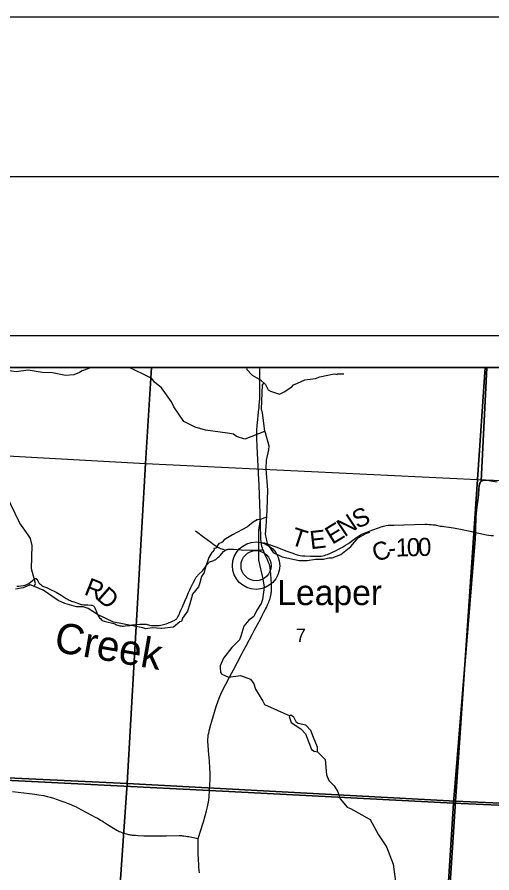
# Model space of a CAD drawing. Extents: x -2.1 to 31.9, y 6.3 to 28.3.
# Drawn here: x 3.259 to 4.749, y 25.658 to 28.344 of the extents above; entities that cross this region are included whole.
import ezdxf

# ---------------------------------------------------------------- set-up
doc = ezdxf.new("R2010")
doc.units = 0
for name, color, linetype in [('Default', 7, 'Continuous'), ('GM_X_County_Road', 7, 'Continuous'), ('GM_X_County_Road_Text', 7, 'Continuous'), ('GM_X_Minor_River', 7, 'Continuous'), ('GM_X_Minor_River_Text', 7, 'Continuous'), ('GM_X_Section', 7, 'Continuous'), ('GM_X_Section_Text', 7, 'Continuous'), ('GM_X_State_Route', 7, 'Continuous'), ('GM_X_Township_Road', 7, 'Continuous'), ('GM_X_Unincorporated', 7, 'Continuous'), ('GM_X_Unincorporated_Location', 7, 'Continuous'), ('GM_X_Unincorporated_Text', 7, 'Continuous'), ('SH_Border', 7, 'Continuous'), ('SH_Cut_Line', 7, 'Continuous'), ('SH_Data', 7, 'Continuous')]:
    doc.layers.add(name, color=color, linetype=linetype)

msp = doc.modelspace()

# ---------------------------------------------------------------- linework, layer by layer
at = {"layer": 'Default'}
for points in [[(3.0763, 25.9555), (3.8625, 25.9158), (4.6286, 25.8765), (4.6962, 26.7048), (4.6976, 26.7271), (4.6976, 26.7313), (4.6974, 26.7458), (4.6982, 26.7628), (4.6989, 26.7745), (4.6998, 26.7857), (4.7008, 26.7966), (4.7027, 26.8132), (4.7045, 26.8279), (4.7064, 26.8439), (4.7081, 26.8648), (4.7086, 26.8693), (4.7092, 26.8741), (4.7097, 26.8767), (4.7104, 26.879), (4.7116, 26.8819), (4.713, 26.8843), (4.7143, 26.8861), (4.7151, 26.8869), (4.7153, 26.887), (4.7331, 27.244), (0.0344, 27.244)], [(6.8344, 27.244), (4.7331, 27.244), (4.7153, 26.887), (4.7151, 26.8869), (4.7143, 26.8861), (4.713, 26.8843), (4.7116, 26.8819), (4.7104, 26.879), (4.7097, 26.8767), (4.7092, 26.8741), (4.7086, 26.8693), (4.7081, 26.8648), (4.7064, 26.8439), (4.7045, 26.8279), (4.7027, 26.8132), (4.7008, 26.7966), (4.6998, 26.7857), (4.6989, 26.7745), (4.6982, 26.7628), (4.6974, 26.7458), (4.6976, 26.7313), (4.6976, 26.7271), (4.6962, 26.7048), (4.6286, 25.8765), (5.5694, 25.8349)], [(6.8344, 20.444), (6.8344, 25.7721), (5.5694, 25.8349), (4.6286, 25.8765), (4.6032, 25.4816), (4.5667, 24.9084), (4.5473, 24.5954), (4.4901, 23.6442), (4.4651, 23.2405)]]:
    msp.add_lwpolyline(points, dxfattribs=at)
for points in [[(3.6804, 27.244), (2.6242, 27.244), (2.6077, 27.001), (3.6616, 26.9432)], [(4.7272, 27.244), (3.6804, 27.244), (3.6616, 26.9432), (4.7032, 26.892)], [(5.7794, 27.244), (4.7272, 27.244), (4.7032, 26.892), (5.7545, 26.8487), (5.7699, 27.0924)], [(0.0344, 26.1105), (0.0344, 20.444), (3.7533, 20.444), (3.8489, 20.5389), (3.9894, 20.6326), (4.16, 20.7203), (4.2895, 20.7662), (4.3023, 20.7658), (4.3091, 20.8714), (4.3751, 21.8979), (4.4168, 22.5238), (4.4383, 22.8067), (4.4651, 23.2405), (4.4901, 23.6442), (4.5473, 24.5954), (4.5667, 24.9084), (4.6032, 25.4816), (4.6286, 25.8765), (3.8625, 25.9158), (3.0763, 25.9555), (2.8034, 25.9683), (2.0757, 26.0047), (0.4641, 26.0883)]]:
    msp.add_lwpolyline(points, close=True, dxfattribs=at)
at = {"layer": 'GM_X_County_Road'}
for points in [[(4.6978, 26.7266), (4.6978, 26.7308), (4.6976, 26.7452), (4.6984, 26.7622), (4.6991, 26.774), (4.7, 26.7852), (4.701, 26.796), (4.7029, 26.8127), (4.7047, 26.8274), (4.7066, 26.8434), (4.7083, 26.8643), (4.7088, 26.8688), (4.7094, 26.8736), (4.7099, 26.8762), (4.7106, 26.8785), (4.7118, 26.8814), (4.7132, 26.8838), (4.7145, 26.8855), (4.7155, 26.8865)], [(4.7155, 26.8865), (4.7165, 26.8873), (4.718, 26.8883), (4.7195, 26.889), (4.7215, 26.8896), (4.724, 26.8901), (4.7264, 26.8903), (4.7298, 26.8902), (4.7346, 26.8899), (4.7452, 26.8886), (4.7657, 26.8849)], [(4.025, 26.6944), (4.0292, 26.6941), (4.0331, 26.6938), (4.0353, 26.6935), (4.0376, 26.693), (4.0418, 26.6917), (4.0498, 26.6888), (4.0711, 26.6809), (4.1055, 26.668), (4.1244, 26.6608), (4.1317, 26.6583), (4.1378, 26.6564), (4.1425, 26.6551), (4.1474, 26.6541), (4.1544, 26.6531), (4.1621, 26.6524), (4.1798, 26.6516), (4.1948, 26.6514), (4.2026, 26.6514), (4.2085, 26.6517), (4.2132, 26.6522), (4.2183, 26.6531), (4.2232, 26.6542), (4.2279, 26.6555), (4.233, 26.6573), (4.2399, 26.6601), (4.2463, 26.663), (4.2584, 26.6689), (4.2695, 26.6744), (4.2796, 26.68), (4.2895, 26.6861), (4.2969, 26.6909), (4.3028, 26.695), (4.3123, 26.7019), (4.3196, 26.7075), (4.3268, 26.7127), (4.3321, 26.7161), (4.337, 26.7189), (4.3426, 26.7217), (4.3483, 26.7242), (4.3559, 26.727), (4.3753, 26.734), (4.3927, 26.741), (4.401, 26.744), (4.4052, 26.7454), (4.409, 26.7465), (4.413, 26.7474), (4.417, 26.748), (4.4238, 26.7487), (4.4308, 26.7491), (4.441, 26.7496), (4.4724, 26.7505), (4.5055, 26.7512), (4.5384, 26.7519), (4.546, 26.7518), (4.5522, 26.7515), (4.5587, 26.7512), (4.565, 26.7506), (4.5713, 26.7497), (4.5866, 26.7464), (4.5924, 26.7455), (4.5983, 26.7447), (4.6134, 26.7431), (4.6212, 26.7421), (4.6286, 26.7409), (4.6338, 26.74), (4.65, 26.7368), (4.6811, 26.7302), (4.6978, 26.7266)], [(4.6978, 26.7266), (4.7077, 26.7244), (4.7317, 26.7193), (4.7393, 26.7179), (4.7463, 26.717), (4.7537, 26.7163)], [(3.7622, 26.4596), (3.7634, 26.4613), (3.7652, 26.4646), (3.7673, 26.4688), (3.77, 26.4754), (3.7729, 26.4822), (3.778, 26.4927), (3.7857, 26.5107), (3.7912, 26.5237), (3.7972, 26.5379), (3.8005, 26.5459), (3.8038, 26.5533), (3.8069, 26.5601), (3.812, 26.57), (3.8176, 26.5796), (3.8212, 26.5854), (3.8236, 26.5889), (3.8248, 26.5906), (3.8261, 26.5922), (3.8274, 26.5937), (3.8287, 26.5951), (3.8301, 26.5962), (3.8394, 26.6048), (3.8418, 26.6073), (3.8443, 26.6101), (3.848, 26.615), (3.8536, 26.6233), (3.8561, 26.6268), (3.858, 26.6291), (3.8593, 26.6307), (3.8606, 26.6318), (3.8621, 26.6329), (3.8637, 26.6339), (3.8654, 26.6347), (3.8673, 26.6355), (3.8761, 26.6383), (3.8778, 26.6391), (3.8796, 26.64), (3.8809, 26.6408), (3.8822, 26.6417), (3.8852, 26.644), (3.8892, 26.6476), (3.893, 26.6512), (3.896, 26.6543), (3.9028, 26.6615), (3.9069, 26.666), (3.9088, 26.6677), (3.9106, 26.669), (3.9129, 26.6705)], [(3.9129, 26.6705), (3.914, 26.6712), (3.9156, 26.672), (3.9172, 26.6726), (3.919, 26.6731), (3.9211, 26.6735), (3.9244, 26.6737), (3.9312, 26.6736), (3.938, 26.6734), (3.9624, 26.6722), (3.9925, 26.671), (4.0011, 26.6706), (4.0124, 26.6702), (4.0156, 26.6702), (4.0187, 26.6702), (4.0218, 26.6706), (4.0243, 26.6712), (4.0267, 26.672), (4.0302, 26.6731)], [(3.2585, 26.5573), (3.2643, 26.5575), (3.2705, 26.5582), (3.2779, 26.5595), (3.2846, 26.5612), (3.2868, 26.5619), (3.2891, 26.5628), (3.2913, 26.5639), (3.2932, 26.565), (3.2968, 26.5674), (3.3058, 26.5746), (3.313, 26.5805), (3.3139, 26.581), (3.315, 26.5813), (3.3161, 26.5815), (3.3172, 26.5815), (3.3183, 26.5812), (3.3194, 26.5805), (3.3202, 26.5798), (3.3211, 26.5787), (3.3238, 26.5741), (3.3276, 26.5685), (3.3304, 26.565), (3.3331, 26.5624), (3.3366, 26.5597), (3.3393, 26.5581), (3.3421, 26.5567), (3.3479, 26.5544), (3.3554, 26.5516), (3.36, 26.5496), (3.3683, 26.5454), (3.3751, 26.5419), (3.3814, 26.5384), (3.3967, 26.5294), (3.4131, 26.5193), (3.4194, 26.5157), (3.4227, 26.5139), (3.426, 26.5124), (3.4299, 26.5109), (3.4401, 26.5072), (3.4517, 26.5031), (3.4577, 26.5011), (3.4603, 26.5004), (3.4632, 26.4999), (3.4688, 26.4993), (3.4806, 26.4986), (3.4899, 26.4982), (3.4928, 26.4979), (3.4947, 26.4975), (3.4962, 26.4969), (3.4977, 26.4961), (3.4993, 26.495), (3.5007, 26.4936), (3.502, 26.4918), (3.5031, 26.4897), (3.5043, 26.4869), (3.5069, 26.4797), (3.509, 26.4739), (3.5112, 26.4685), (3.5135, 26.4644), (3.5157, 26.4612), (3.518, 26.4584), (3.5205, 26.4557), (3.5232, 26.4532), (3.5261, 26.4511), (3.5289, 26.4493), (3.5324, 26.4479), (3.5361, 26.4465), (3.5404, 26.4454), (3.5583, 26.4415), (3.5622, 26.4404), (3.5658, 26.439), (3.5709, 26.4367), (3.5747, 26.4352), (3.5778, 26.4341), (3.5813, 26.4333), (3.5853, 26.4328), (3.5891, 26.4325), (3.593, 26.4325), (3.5978, 26.4329), (3.6129, 26.4347), (3.6199, 26.4358), (3.6256, 26.4363), (3.644, 26.4379), (3.6568, 26.4387), (3.6602, 26.4386), (3.6638, 26.4382), (3.6744, 26.4355), (3.6803, 26.4344), (3.685, 26.434), (3.6896, 26.4338), (3.6972, 26.4339), (3.705, 26.4344), (3.7097, 26.435), (3.714, 26.4359), (3.7182, 26.437), (3.7264, 26.4395), (3.7317, 26.4414), (3.736, 26.4431), (3.7408, 26.4451), (3.7488, 26.4484), (3.7515, 26.4498), (3.7539, 26.4511), (3.756, 26.4526), (3.758, 26.4545), (3.7599, 26.4565), (3.7616, 26.4587), (3.7622, 26.4596)]]:
    msp.add_lwpolyline(points, dxfattribs=at)
at = {"layer": 'GM_X_Minor_River'}
for points in [[(3.4872, 27.244), (3.4836, 27.2407), (3.463, 27.2341), (3.4549, 27.2283), (3.4369, 27.2209), (3.4112, 27.2191), (3.3695, 27.2272), (3.3374, 27.2286), (3.2937, 27.2357), (3.2558, 27.2305), (3.2272, 27.2344), (3.2108, 27.244)], [(4.0348, 27.0434), (3.9736, 27.0188), (3.947, 27.0272), (3.9382, 27.0344), (3.9194, 27.038), (3.8505, 27.0474), (3.8175, 27.0572), (3.7822, 27.0747), (3.751, 27.1209), (3.7439, 27.1363), (3.7116, 27.1798), (3.6902, 27.198), (3.6815, 27.2093), (3.6544, 27.2235), (3.6108, 27.244)], [(3.9783, 27.244), (3.9802, 27.2383), (3.9961, 27.2201), (4.0188, 27.2076), (4.0226, 27.2054), (4.0385, 27.1906), (4.0464, 27.1742), (4.054, 27.1697), (4.0823, 27.1606), (4.0975, 27.1679), (4.1213, 27.1832), (4.1262, 27.1896), (4.1383, 27.1946), (4.1621, 27.2053), (4.1949, 27.2092), (4.2089, 27.2149), (4.2539, 27.2242), (4.2596, 27.223), (4.263, 27.2219), (4.2637, 27.2242), (4.2845, 27.2242)], [(4.033, 27.1957), (4.0279, 27.1898), (4.0251, 27.1129)], [(4.0251, 27.1129), (4.0276, 27.1031), (4.0348, 27.0434), (4.0375, 27.04), (4.0493, 26.9986), (4.0481, 26.9861), (4.0402, 26.953), (4.0395, 26.9256), (4.0445, 26.8587), (4.043, 26.7986), (4.0427, 26.7952), (4.0393, 26.7446), (4.0378, 26.7207), (4.0439, 26.6914), (4.0625, 26.663), (4.0905, 26.6497), (4.1441, 26.6377), (4.1691, 26.6381), (4.1948, 26.6424), (4.2209, 26.6424), (4.2368, 26.6467), (4.2473, 26.6471), (4.2753, 26.6574), (4.29, 26.67), (4.3067, 26.6825), (4.3289, 26.7092), (4.3463, 26.7188), (4.3501, 26.7222), (4.3656, 26.7272)], [(3.3127, 26.5563), (3.3165, 26.5664), (3.3037, 26.6119), (3.3059, 26.6848), (3.3008, 26.7068), (3.2939, 26.7189), (3.2679, 26.7556), (3.2241, 26.8439), (3.2137, 26.8564), (3.1623, 26.8937), (3.1473, 26.9149), (3.1299, 26.9687)], [(4.0413, 26.7741), (4.023, 26.767), (4.0098, 26.7655), (4.0125, 26.7655), (3.9992, 26.759), (3.9819, 26.7438), (3.9346, 26.7189), (3.9086, 26.7029), (3.9025, 26.6953), (3.901, 26.6972), (3.8999, 26.6941), (3.8923, 26.6915), (3.8825, 26.6774), (3.8761, 26.6755), (3.8772, 26.672), (3.8716, 26.6656), (3.8697, 26.6629), (3.8602, 26.6481), (3.8486, 26.6142), (3.8463, 26.6009), (3.8376, 26.5883), (3.832, 26.5678), (3.8282, 26.556), (3.8093, 26.5324), (3.801, 26.5019), (3.7939, 26.4791), (3.7784, 26.4574), (3.7743, 26.4468), (3.7701, 26.4452), (3.7493, 26.4292), (3.713, 26.4246), (3.7104, 26.4246), (3.6824, 26.4264), (3.6631, 26.4241), (3.6537, 26.4267), (3.5792, 26.4414), (3.5611, 26.4444), (3.5108, 26.4682), (3.482, 26.4871), (3.4665, 26.4924), (3.4453, 26.4931), (3.409, 26.5033), (3.3878, 26.5131), (3.3406, 26.5446), (3.2974, 26.5627), (3.2975, 26.5604), (3.2804, 26.5532), (3.2778, 26.5528), (3.2536, 26.5478)], [(4.0215, 26.7669), (4.0164, 26.7337), (4.0164, 26.6714), (4.0162, 26.6388), (4.0303, 26.581), (4.0341, 26.5547), (4.0287, 26.5157), (4.0246, 26.5037), (4.0111, 26.4825), (4.0018, 26.4627), (3.9856, 26.4506), (3.9703, 26.4321), (3.9614, 26.4009), (3.9565, 26.3893), (3.9327, 26.365), (3.9068, 26.3316), (3.8966, 26.308), (3.8965, 26.3031), (3.8971, 26.2868), (3.9011, 26.2809), (3.922, 26.2723), (3.9595, 26.2768), (3.9917, 26.2655), (4.0015, 26.2508), (4.0066, 26.2347), (4.0297, 26.1971), (4.0354, 26.1859), (4.1149, 26.1506)], [(4.1188, 26.1297), (4.1491, 26.1093), (4.1634, 26.0941), (4.1743, 26.0671), (4.1824, 26.0452), (4.1916, 26.0393), (4.2018, 26.0378), (4.2015, 26.0522), (4.1892, 26.0826), (4.1807, 26.1045), (4.1654, 26.121), (4.1406, 26.1263), (4.1358, 26.1299), (4.1268, 26.1461), (4.1176, 26.1529), (4.1129, 26.1489), (4.1188, 26.1297)], [(4.2018, 26.0378), (4.2256, 26.0131), (4.2298, 25.9651), (4.2376, 25.9478), (4.2541, 25.9309), (4.2656, 25.912), (4.2729, 25.8897), (4.2948, 25.8636), (4.3051, 25.8602)], [(4.3051, 25.8602), (4.367, 25.8252), (4.3931, 25.7771), (4.4184, 25.7389), (4.4385, 25.6855), (4.4488, 25.6145), (4.455, 25.5887), (4.4627, 25.5724)]]:
    msp.add_lwpolyline(points, dxfattribs=at)
at = {"layer": 'GM_X_Section'}
for points in [[(2.6051, 27.0012), (2.6077, 27.001), (3.6616, 26.9432), (3.6038, 25.9379), (2.5466, 25.9887)], [(3.6616, 26.9432), (4.7032, 26.892), (4.6345, 25.8828), (3.6038, 25.9379)], [(4.7032, 26.892), (5.7545, 26.8487), (5.7377, 26.5914), (5.7216, 26.3472), (5.7057, 26.0946), (5.6902, 25.8357), (4.6345, 25.8828)], [(2.5466, 25.9887), (3.6038, 25.9379), (3.5328, 24.9185), (2.4786, 24.9709)], [(3.6038, 25.9379), (4.6345, 25.8828), (4.5692, 24.8661), (3.5328, 24.9185)], [(4.6345, 25.8828), (5.6902, 25.8357), (5.6296, 24.8273), (4.5692, 24.8661)]]:
    msp.add_lwpolyline(points, close=True, dxfattribs=at)
at = {"layer": 'GM_X_State_Route'}
for points in [[(3.8627, 25.9153), (3.8629, 25.9186), (3.8638, 25.9356), (3.8646, 25.9511), (3.8647, 25.9692), (3.8642, 25.9872), (3.8629, 26.0083), (3.8621, 26.0189), (3.8595, 26.0414), (3.858, 26.0591), (3.8576, 26.0689), (3.8576, 26.0772), (3.8583, 26.085), (3.859, 26.0907), (3.8601, 26.0967), (3.8625, 26.1078), (3.8665, 26.1232), (3.8695, 26.1336), (3.8838, 26.1803), (3.8898, 26.1979), (3.8951, 26.2111), (3.9018, 26.2258), (3.9269, 26.2743), (3.9377, 26.2953), (3.963, 26.343), (3.9686, 26.3537), (3.9773, 26.3699), (3.9978, 26.4082), (4.0032, 26.4181), (4.0133, 26.4373), (4.0223, 26.4542), (4.027, 26.4636), (4.0301, 26.4697), (4.0332, 26.4757), (4.0384, 26.4856), (4.0412, 26.491), (4.0449, 26.4989), (4.0488, 26.5079), (4.0503, 26.5118), (4.0515, 26.5155), (4.0539, 26.5246), (4.056, 26.5338), (4.0566, 26.5378), (4.057, 26.5412), (4.0577, 26.5502), (4.0575, 26.5618), (4.0562, 26.583), (4.0553, 26.5935), (4.0539, 26.6076), (4.0533, 26.6124), (4.0526, 26.6171), (4.0518, 26.6207), (4.0506, 26.6254), (4.0483, 26.6324), (4.0448, 26.6407), (4.0355, 26.6607), (4.0342, 26.6635), (4.0317, 26.6691), (4.0302, 26.6731), (4.0286, 26.6774), (4.0272, 26.6819), (4.0257, 26.6891), (4.025, 26.6944), (4.0244, 26.6985), (4.024, 26.7041), (4.0238, 26.7164), (4.0231, 26.7416), (4.0218, 26.787), (4.0187, 26.8741), (4.0168, 26.9126), (4.0123, 26.9976), (4.0114, 27.0204), (4.0112, 27.0286), (4.0111, 27.0331), (4.0116, 27.0471), (4.0124, 27.0619), (4.0143, 27.0804), (4.0157, 27.0937), (4.0169, 27.1049), (4.0183, 27.119), (4.0188, 27.1236), (4.0199, 27.1378), (4.0201, 27.1442), (4.0203, 27.1681), (4.0202, 27.1933), (4.0205, 27.2179), (4.0209, 27.238), (4.0212, 27.244)], [(3.244, 25.9133), (3.2982, 25.907), (3.3142, 25.905), (3.3276, 25.9029), (3.3425, 25.9001), (3.3531, 25.8976), (3.3627, 25.8948), (3.3727, 25.8917), (3.385, 25.8877), (3.3963, 25.8838), (3.4082, 25.8796), (3.4193, 25.8753), (3.428, 25.8719), (3.4336, 25.8695), (3.4386, 25.8671), (3.4438, 25.8646), (3.4584, 25.8569), (3.492, 25.8392), (3.5044, 25.8329), (3.5112, 25.8294), (3.5164, 25.8264), (3.5211, 25.8234), (3.5265, 25.82), (3.5422, 25.8097), (3.5671, 25.7945), (3.5723, 25.7916), (3.5756, 25.7899), (3.5793, 25.788), (3.5837, 25.7861), (3.5898, 25.7836), (3.5938, 25.7822), (3.5978, 25.781), (3.6019, 25.7798), (3.6056, 25.7788), (3.6085, 25.7782), (3.6111, 25.7777), (3.6138, 25.7772), (3.6167, 25.7767), (3.6203, 25.7763), (3.6229, 25.776), (3.6306, 25.7755), (3.6393, 25.775), (3.657, 25.7741), (3.6784, 25.7738), (3.728, 25.7735), (3.7671, 25.7747), (3.7707, 25.7746), (3.7744, 25.7745), (3.7781, 25.7742), (3.7818, 25.774), (3.788, 25.7732), (3.7934, 25.7723), (3.7983, 25.7714), (3.8163, 25.7678), (3.8275, 25.7655)], [(3.8275, 25.7655), (3.8282, 25.7685), (3.829, 25.7715), (3.8332, 25.7852), (3.8437, 25.8183), (3.849, 25.8364), (3.8532, 25.8525), (3.8563, 25.8653), (3.8583, 25.8753), (3.8601, 25.8862), (3.8613, 25.898), (3.8627, 25.9153)], [(3.8313, 25.6574), (3.8302, 25.666), (3.8293, 25.6771), (3.8288, 25.6852), (3.8283, 25.6972), (3.8275, 25.7195), (3.8269, 25.7434), (3.8269, 25.757), (3.8271, 25.762), (3.8275, 25.7655)]]:
    msp.add_lwpolyline(points, dxfattribs=at)
at = {"layer": 'GM_X_Township_Road'}
msp.add_lwpolyline([(3.8186, 26.7312), (3.8298, 26.7228), (3.8403, 26.715), (3.8558, 26.7038), (3.8665, 26.6957), (3.8773, 26.6875), (3.8824, 26.684), (3.8861, 26.6817), (3.8904, 26.6793), (3.8937, 26.6777), (3.8973, 26.6762), (3.901, 26.6748), (3.9129, 26.6705)], dxfattribs=at)
at = {"layer": 'GM_X_Unincorporated'}
for radius in [0.0744, 0.0472]:
    msp.add_circle((4.0088, 26.622), radius, dxfattribs=at)
at = {"layer": 'GM_X_Unincorporated_Location'}
msp.add_line((4.0088, 26.622), (4.0088, 26.622), dxfattribs=at)
at = {"layer": 'SH_Border'}
msp.add_lwpolyline([(-0.5656, 27.844), (31.4344, 27.844), (31.4344, 6.844), (-0.5656, 6.844)], close=True, dxfattribs=at)
at = {"layer": 'SH_Cut_Line'}
msp.add_lwpolyline([(-2.0656, 6.344), (31.9344, 6.344), (31.9344, 28.344), (-2.0656, 28.344)], close=True, dxfattribs=at)
msp.add_lwpolyline([(6.8344, 20.444), (6.8344, 27.244), (0.0344, 27.244), (0.0344, 20.444)], dxfattribs=at)
at = {"layer": 'SH_Data'}
for p, q in [((-0.0656, 27.344), (6.9344, 27.344)), ((0.0344, 27.244), (6.8344, 27.244))]:
    msp.add_line(p, q, dxfattribs=at)

# ---------------------------------------------------------------- texts
at = {"layer": 'GM_X_County_Road_Text'}
for s, rotation, p in [('N', 33.8168, (4.2864, 26.7104)), ('S', 23.6824, (4.3257, 26.737)), ('E', 31.3233, (4.2479, 26.6869)), ('T', 341.992, (4.1138, 26.6893)), ('E', 6.3632, (4.1802, 26.6735)), ('1', 1.2465, (4.4474, 26.6505)), ('0', 1.2387, (4.4824, 26.6513)), ('0', 1.2308, (4.5174, 26.6521)), ('C', 21.0284, (4.3858, 26.6321)), ('-', 6.6661, (4.4257, 26.6479)), ('R', 338.3562, (3.4663, 26.5327)), ('D', 318.7764, (3.5054, 26.5182))]:
    msp.add_text(s, height=0.0568, rotation=rotation, dxfattribs=at).set_placement(p)
at = {"layer": 'GM_X_Minor_River_Text'}
msp.add_text('Creek', height=0.0947, rotation=349.9986, dxfattribs=at).set_placement((3.3719, 26.3531))
at = {"layer": 'GM_X_Section_Text'}
msp.add_text('7', height=0.0419, rotation=0, dxfattribs=at).set_placement((4.1337, 26.3823))
at = {"layer": 'GM_X_Unincorporated_Text'}
msp.add_text('Leaper', height=0.07898, rotation=0, dxfattribs=at).set_placement((4.0753, 26.4983))

doc.saveas('drawing.dxf')
